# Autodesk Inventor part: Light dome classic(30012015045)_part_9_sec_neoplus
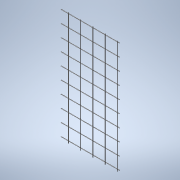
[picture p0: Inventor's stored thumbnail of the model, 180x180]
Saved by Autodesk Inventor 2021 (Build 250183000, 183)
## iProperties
Created: 2026-04
Part Number: Light dome classic(30012015045)_part_9_sec_neoplus
Material: Generic
Catalog Web Link: www.3dfindit.com
Description: Light dome classic_part_9_sec_neoplus-
Vendor: KINGSPAN
Document SubType Name: Modeling
Designer: psAdmin
Manufacturer: KINGSPAN
Mass: 184.301 g
Surface Area: 1482.6 cm^2
Volume: 184.301 cm^3
Density: 1 g/cm^3
Appearance: PSOLRGB-255-255-255
Category: PARTsolutions
Company: KINGSPAN
Title: Light dome classic(30012015045)_part_9_sec_neoplus
Author: Cadenas PARTsolutions
PSOL_IDENT_0: {$CADENAS_DATA/23d-libs/kingspan_kla/light_dome_classic_neoplus/parts/part_9_sec.prj},290 {VTYP=3D},
PSOL_IDENT_1: {NB=Light dome classic(30012015045)_part_9_sec_neoplus},{LINA=Light dome classic(30012015045)_part_9
PSOL_IDENT_2: _sec_neoplus},{NN=Light dome classic_part_9_sec_neoplus},{DATE=15.07.2024 10:56:16},{GEOMDATE=28.06.
PSOL_IDENT_3: 2024 11:51:14},{VERSION=},{LINEID=10},{WBVAR=LODLEVEL,L,W,DP,OP},{WBNUMERIC=W}  {NB=Light dome class
PSOL_IDENT_4: ic(30012015045)_part_9_sec_neoplus},{LINA=Light dome classic(30012015045)_part_9_sec_neoplus},{KT=DU
PSOL_IDENT_5: MMY},{IDNR=},{PN=Light dome classic},{LODLEVEL=300},{L=120},{W=150},{WX=120,150,180,240,270,300},{LX=
PSOL_IDENT_6: 1200},{XWX=1500},{DP=4},{OPX='5','Pneumatic - NRWG F.6 LK'},{OP=5},{DRIVE=1},{DPX='1', 'Natural vent
PSOL_IDENT_7: ilation', '2' , 'NSHEV (natural smoke, heat exhaust ventilation)', '3', 'Fixed','4','NSHE'}
NB: Light dome classic(30012015045)_part_9_sec_neoplus
NN: Light dome classic_part_9_sec_neoplus
NBSYN: $PN.($LODLEVEL.$L.$W.$DP.$OP.)_part_9_sec_neoplus
LINA: Light dome classic(30012015045)_part_9_sec_neoplus
CATALOG: Light + Air
PN: Light dome classic
LODLEVEL: 300
L: 120
W: 150
DP: NSHE
OP: Pneumatic - NRWG F.6 LK
SUPPLIER: KINGSPAN
ARTICLENO: Light dome classic(30012015045)_part_9_sec_neoplus
BOMINFO: Light dome classic(30012015045)_part_9_sec_neoplus
CREATOR: CADENAS GmbH
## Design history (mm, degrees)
sketch "Sketch_8"
  geometry: C1 r 2.5 at (450, 263.34); 1 further point
  constraints: 1 centre point
extrude "Extrusion1" join sketch "Sketch_8" stored distance "d0" = 1225; taper "d1" = 0 deg
sketch "Sketch_1"
  geometry: C1 r 2.5 at (-600, 268.32); 1 further point
  constraints: 1 centre point
extrude "Extrusion2" join sketch "Sketch_1" stored distance "d2" = 925; taper "d3" = 0 deg
pattern_linear "Rectangular Pattern1" dims "d6" = 100, "d9" = 0
sketch "Sketch_2"
  geometry: C1 r 2.5 at (350, 263.34); 1 further point
  constraints: 1 centre point
extrude "Extrusion3" join sketch "Sketch_2" stored distance "d10" = 1225; taper "d11" = 0 deg
pattern_linear "Rectangular Pattern2" dims "d14" = 100, "d17" = 0
sketch "Sketch_9"
  geometry: L1 (-10, -278.32)-(10, -278.32); L2 (10, -278.32)-(10, -258.32); L3 (10, -258.32)-(-10, -258.32); L4 (-10, -258.32)-(-10, -278.32)
  constraints: 8 end point
extrude "Extrusion4" cut sketch "Sketch_9" stored distance "d18" = 220; taper "d19" = 0 deg
sketch "Sketch_10"
  geometry: L1 (-500, 497.5)-(-500, -497.5); L2 (-500, -497.5)-(0, -497.5); L3 (0, -497.5)-(0, 497.5); L4 (0, 497.5)-(-500, 497.5)
  constraints: 8 end point
extrude "Extrusion5" cut sketch "Sketch_10" distance "d20" = 1635; taper "d21" = 0 deg
node "IP_9_sec_XY"
node "IP_9_sec_YZ"
node "IP_9_sec_ZX"
node "IP_9_sec_X"
node "IP_9_sec_Y"
node "IP_9_sec_Z"
node "IP_9_sec_Center"
body "Solid1"
